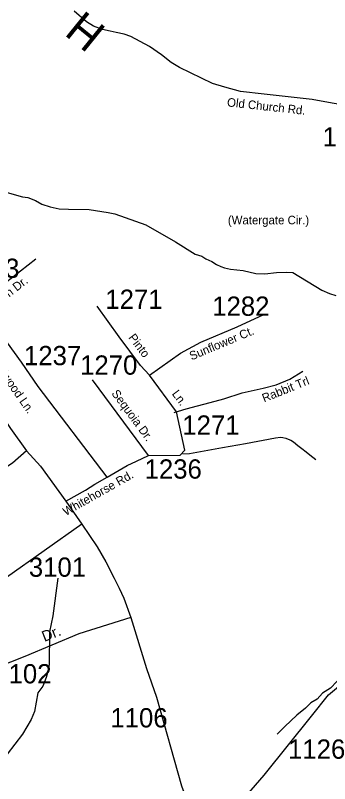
# Model space of a CAD drawing. Extents: x 1268485 to 1426702, y 514839 to 616766.
# Drawn here: x 1323145 to 1325557, y 534404 to 540290 of the extents above; entities that cross this region are included whole.
import ezdxf

# ---------------------------------------------------------------- set-up
doc = ezdxf.new("R2010")
doc.units = 0
for name, color, linetype in [('Old_Level_10', 7, 'Continuous'), ('Old_Level_11', 7, 'Continuous'), ('Old_Level_22', 7, 'Continuous'), ('Old_Level_32', 7, 'Continuous'), ('Old_Level_35', 7, 'Continuous'), ('Old_Level_62', 7, 'Continuous'), ('Old_Level_8', 7, 'Continuous')]:
    doc.layers.add(name, color=color, linetype=linetype)

msp = doc.modelspace()

# ---------------------------------------------------------------- linework, layer by layer
at = {"layer": 'Old_Level_32'}
for p, q in [((1322867.165, 538086.22), (1323303.025, 538423.789)), ((1324167.542, 536916.627), (1323736.963, 537498.634)), ((1324167.542, 536916.627), (1324409.493, 536919.535)), ((1323531.515, 536567.967), (1323656.067, 536390.941))]:
    msp.add_line(p, q, dxfattribs=at)
for points in [[(1325986.882, 539550.501), (1325575.826, 539615.973), (1325423.495, 539644.448), (1325053.554, 539684.979), (1324872.765, 539706.754), (1324752.239, 539740.756), (1324658.497, 539767.555), (1324404.054, 539891.503), (1324340.442, 539928.351), (1324265.114, 539986.975), (1324173.961, 540050.982), (1324031.047, 540128.223), (1323979.52, 540144.571), (1323919.195, 540159.661), (1323871.437, 540168.463), (1323812.811, 540181.51), (1323744.504, 540207.446), (1323691.719, 540240.141), (1323594.948, 540323.137)], [(1323849.822, 536752.314), (1323320.972, 537447.076), (1323190.897, 537632.809), (1322974.732, 537928.324), (1322867.165, 538086.22)], [(1324175.36, 537533.095), (1324106.453, 537608.541), (1323940.56, 537827.348), (1323772.004, 538062.234)], [(1324175.36, 537533.095), (1324412.841, 537702.413), (1324567.42, 537786.39), (1324846.758, 537903.109), (1325051.177, 537999.217)], [(1322559.115, 537866.233), (1322685.049, 537706.379), (1322778.05, 537581.004), (1322784.333, 537573.459), (1322899.557, 537419.208), (1323019.849, 537249.604), (1323107.335, 537123.77), (1323230.572, 536954.218)], [(1324409.493, 536919.535), (1324444.647, 536959.734), (1324382.149, 537252.55), (1324175.36, 537533.095)], [(1323230.572, 536954.218), (1323121.915, 536859.334), (1322828.418, 536668.392), (1322585.763, 536514.002), (1322465.113, 536432.263), (1322237.046, 536283.747)], [(1323230.572, 536954.218), (1323336.683, 536836.802), (1323531.515, 536567.967)], [(1323849.822, 536752.314), (1324003.79, 536840.808), (1324073.335, 536875.57), (1324167.542, 536916.627)], [(1323531.515, 536567.967), (1323683.624, 536652.688), (1323755.115, 536698.691), (1323849.822, 536752.314)], [(1323656.067, 536390.941), (1323076.531, 535983.578), (1322929.489, 535889.265), (1322762.339, 535766.029), (1322622.364, 535686.254)], [(1323656.067, 536390.941), (1323771.975, 536219.173), (1323839.412, 536102.617), (1323902.635, 535977.88), (1323942.675, 535901.198), (1323976.394, 535823.494), (1324031.369, 535676.8)], [(1324598.082, 533835.899), (1324675.169, 533989.571), (1324753.197, 534096.273), (1324854.633, 534239.41), (1325054.804, 534468.394), (1325417.737, 534919.958), (1325548.625, 535083.943), (1325674.172, 535188.628), (1325716.022, 535217.941), (1325816.461, 535284.939), (1325854.125, 535305.876), (1325942.008, 535364.5), (1326134.295, 535452.946), (1326247.508, 535490.122), (1326339.77, 535538.828), (1326469.309, 535619.932), (1326516.634, 535650.734), (1326545.244, 535671.554), (1326571.253, 535705.387), (1326778.994, 536013.548), (1327019.384, 536383.177)], [(1324031.369, 535676.8), (1323850.96, 535621.414), (1323633.128, 535550.954), (1323216.691, 535378.863), (1322884.976, 535247.558), (1322543.033, 535114.513), (1322257.746, 535017.685), (1322238.895, 535021.96), (1322222.556, 535034.033), (1322187.367, 535074.273), (1322116.988, 535178.646), (1322007.648, 535337.093), (1321976.609, 535379.446)], [(1324031.369, 535676.8), (1324151.31, 535284.676), (1324227.177, 535065.877), (1324419.85, 534386.148), (1324512.867, 534137.116), (1324598.082, 533835.899)]]:
    msp.add_lwpolyline(points, dxfattribs=at)
at = {"layer": 'Old_Level_35'}
for points in [[(1324362.509, 537247.737), (1324454.578, 537275.624), (1324542.34, 537298.334), (1324640.662, 537322.683), (1324745.547, 537351.135), (1324884.367, 537397.425), (1325047.588, 537433.976), (1325146.731, 537460.017), (1325249.975, 537503.078), (1325351.475, 537563.979)], [(1324431.099, 536930.316), (1324481.542, 536932.726), (1324735.704, 536979.888), (1324912.049, 537009.108), (1325141.912, 537052.989), (1325180.154, 537057.038), (1325198.712, 537055.45), (1325219.832, 537049.759), (1325239.414, 537043.249), (1325259.715, 537034.329), (1325278.374, 537022.129), (1325312.516, 536995.318), (1325343.376, 536970.916), (1325375.877, 536945.747), (1325404.276, 536922.986), (1325451.336, 536887.307)]]:
    msp.add_lwpolyline(points, dxfattribs=at)
at = {"layer": 'Old_Level_62'}
for points in [[(1323047.305, 538942.851), (1323198.429, 538899.585), (1323240.362, 538893.844), (1323299.724, 538870.468), (1323349.244, 538844.016), (1323412.811, 538822.229), (1323480.478, 538808.593), (1323552.451, 538804.646), (1323710.444, 538803.108), (1323857.979, 538779.63), (1323907.704, 538768.813), (1324145.974, 538685.203), (1324373.069, 538555.918), (1324524.91, 538460.159), (1324574.636, 538445.19), (1324606.111, 538424.018), (1324651.735, 538403.41), (1324687.209, 538380.547), (1324720.838, 538365.117), (1324750.57, 538354.66), (1324796.502, 538345.535), (1324892.261, 538335.385), (1324989.764, 538312.931), (1325059.789, 538309.856), (1325150.012, 538319.544), (1325228.137, 538322.056), (1325274.068, 538318.673), (1325497.062, 538185.389), (1325556.425, 538157.912), (1325604.202, 538142.994)], [(1323470.533, 535976.824), (1323431.88, 535689.546), (1323407.069, 535566.156), (1323403.276, 535316.761), (1323396.201, 535270.932), (1323380.925, 535217.055), (1323355.396, 535149.49), (1323318.076, 535098.535), (1323292.753, 534957.049), (1323267.326, 534895.226), (1323198.736, 534782.55), (1323081.036, 534629.786)], [(1327057.304, 534977.349), (1326941.142, 534972.325), (1326735.064, 534973.146), (1326665.244, 534978.682), (1326510.122, 535021.999), (1326389.244, 535072.852), (1326327.933, 535106.07), (1326119.395, 535169.38), (1326035.427, 535176.813), (1325896.196, 535210.801), (1325734.41, 535227.974), (1325649.826, 535204.239), (1325611.379, 535185.323), (1325564.114, 535136.213), (1325501.266, 535095.664), (1325460.153, 535052.142), (1325411.453, 535021.948), (1325370.545, 534982.578), (1325305.236, 534928.085), (1325213.168, 534842.117), (1325153.805, 534781.78)]]:
    msp.add_lwpolyline(points, dxfattribs=at)

# ---------------------------------------------------------------- texts
at = {"layer": 'Old_Level_10'}
msp.add_text('Rabbit Trl', height=65.6167, rotation=21.9496167, dxfattribs=at).set_placement((1325053.917, 537323.775))
at = {"layer": 'Old_Level_11'}
for s, height, rotation, p in [('Old Church Rd.', 65.61666, 353.7475083, (1324766.793, 539593.229)), ('Aspen Dr.', 65.6167, 37.7574389, (1322939.574, 538005.507)), ('Sunflower Ct.', 65.61666, 22.6772167, (1324497.224, 537645.901)), ('Pinto ', 65.6167, 307.1684472, (1324009.054, 537820.28)), ('Redwood Ln.', 65.61666, 305.0047194, (1322945.504, 537656.127)), ('Sequoia Dr.', 65.61666, 306.4947528, (1323879.226, 537392.495)), ('Ln. ', 65.6167, 306.3938806, (1324342.819, 537390.095)), ('Whitehorse Rd.', 65.61666, 29.5185944, (1323532.343, 536453.151)), ('Tekoa               Dr.', 82.02083, 21.5955444, (1322659.246, 535208.616))]:
    msp.add_text(s, height=height, rotation=rotation, dxfattribs=at).set_placement(p)
msp.add_text('(Watergate Cir.)', height=65.61666, dxfattribs=at).set_placement((1324775.5, 538688.85))
at = {"layer": 'Old_Level_22'}
msp.add_text('H', height=246.062, rotation=140.9744778, dxfattribs=at).set_placement((1323852.425, 540186.382))
at = {"layer": 'Old_Level_8'}
for s, p in [('1265', (1325502.522, 539285.667)), ('1263', (1322737.052, 538278.342)), ('1271', (1323835.269, 538041.282)), ('1282', (1324655.84, 537988.135)), ('1237', (1323211.121, 537609.682)), ('1270', (1323641.96, 537536.924)), ('1271', (1324426.234, 537077.221)), ('1236', (1324136.648, 536740.653)), ('3101', (1323248.346, 535988.76)), ('3102', (1322982.984, 535171.78)), ('1106', (1323874.121, 534834.495)), ('1126', (1325237.539, 534594.629))]:
    msp.add_text(s, height=147.6375, dxfattribs=at).set_placement(p)

doc.saveas('drawing.dxf')
